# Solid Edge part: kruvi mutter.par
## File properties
Author: Mac
Template: Normal.par
Last saved by: Mac
Revision: 3
Application: Solid Edge
Material: Aluminum, 1060
Face Style: Aluminum
Fill Style: ANSI38(Aluminum)
Virtual Style: Polished aluminum
Coef. of Thermal Exp: 2.3e-05
Thermal Conductivity: 221.0
Specific Heat: 920.0
Modulus of Elasticity: 68947570000.0
Poission's Ratio: 0.33
Yield Stress: 27579028.0
Ultimate Stress: 68947570.0
Elongation: 0.0
Density: 2712,000 kg/m^3
Accuracy: 0,990
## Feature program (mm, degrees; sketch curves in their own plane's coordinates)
sketch for "unnamed RevolvedProtrusion 1" plane through (0, 0, 0) normal (0, -1, 0) x-axis (1, 0, 0)
  line (0.2, 0.75) -> (0.2409, 0.75)
  arc centre (0.2409, 0.74) radius 0.01 from (0.2409, 0.75) to (0.2508, 0.7409) cw
  line (0.2508, 0.7409) -> (0.3, 0.2)
  line (0.3, 0.2) -> (0.3, 0)
  line (0.3, 0) -> (0.2, 0)
  line (0.2, 0.2) -> (0.2, 0)
  line (0.2, 0.75) -> (0.2, 0.2)
revolve "unnamed RevolvedProtrusion 1" add finite 360 deg
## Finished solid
Body 1: solid body, 6 faces, 6 edges, 0 vertices.
  Faces by surface: cylinder 2, plane 2, cone 1, torus 1
  Edges by curve: circle 6
Bounding box of the edges (mm; curved faces can reach further): 0.600 x 0.600 x 0.750, from (-0.3, -0.3, 0) to (0.3, 0.3, 0.75).
Cylindrical faces by radius (mm): R0.2 x1, R0.3 x1
Conical faces (half-angle, radius in mm at the cone's reference point): 5.1944 deg R0.2508 x1
Toroidal faces (ring radius, tube radius in mm): R0.2409 r0.01 x1
Planar faces by outward normal: +z 1, -z 1
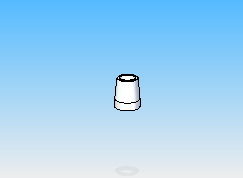
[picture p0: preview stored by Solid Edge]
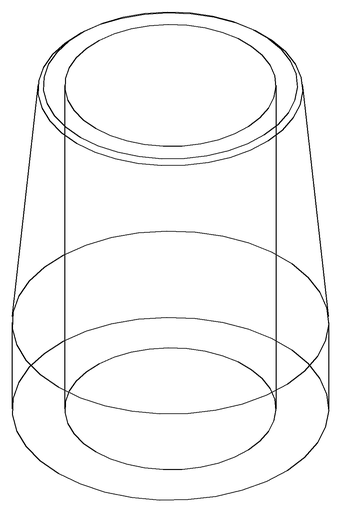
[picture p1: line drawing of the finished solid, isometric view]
